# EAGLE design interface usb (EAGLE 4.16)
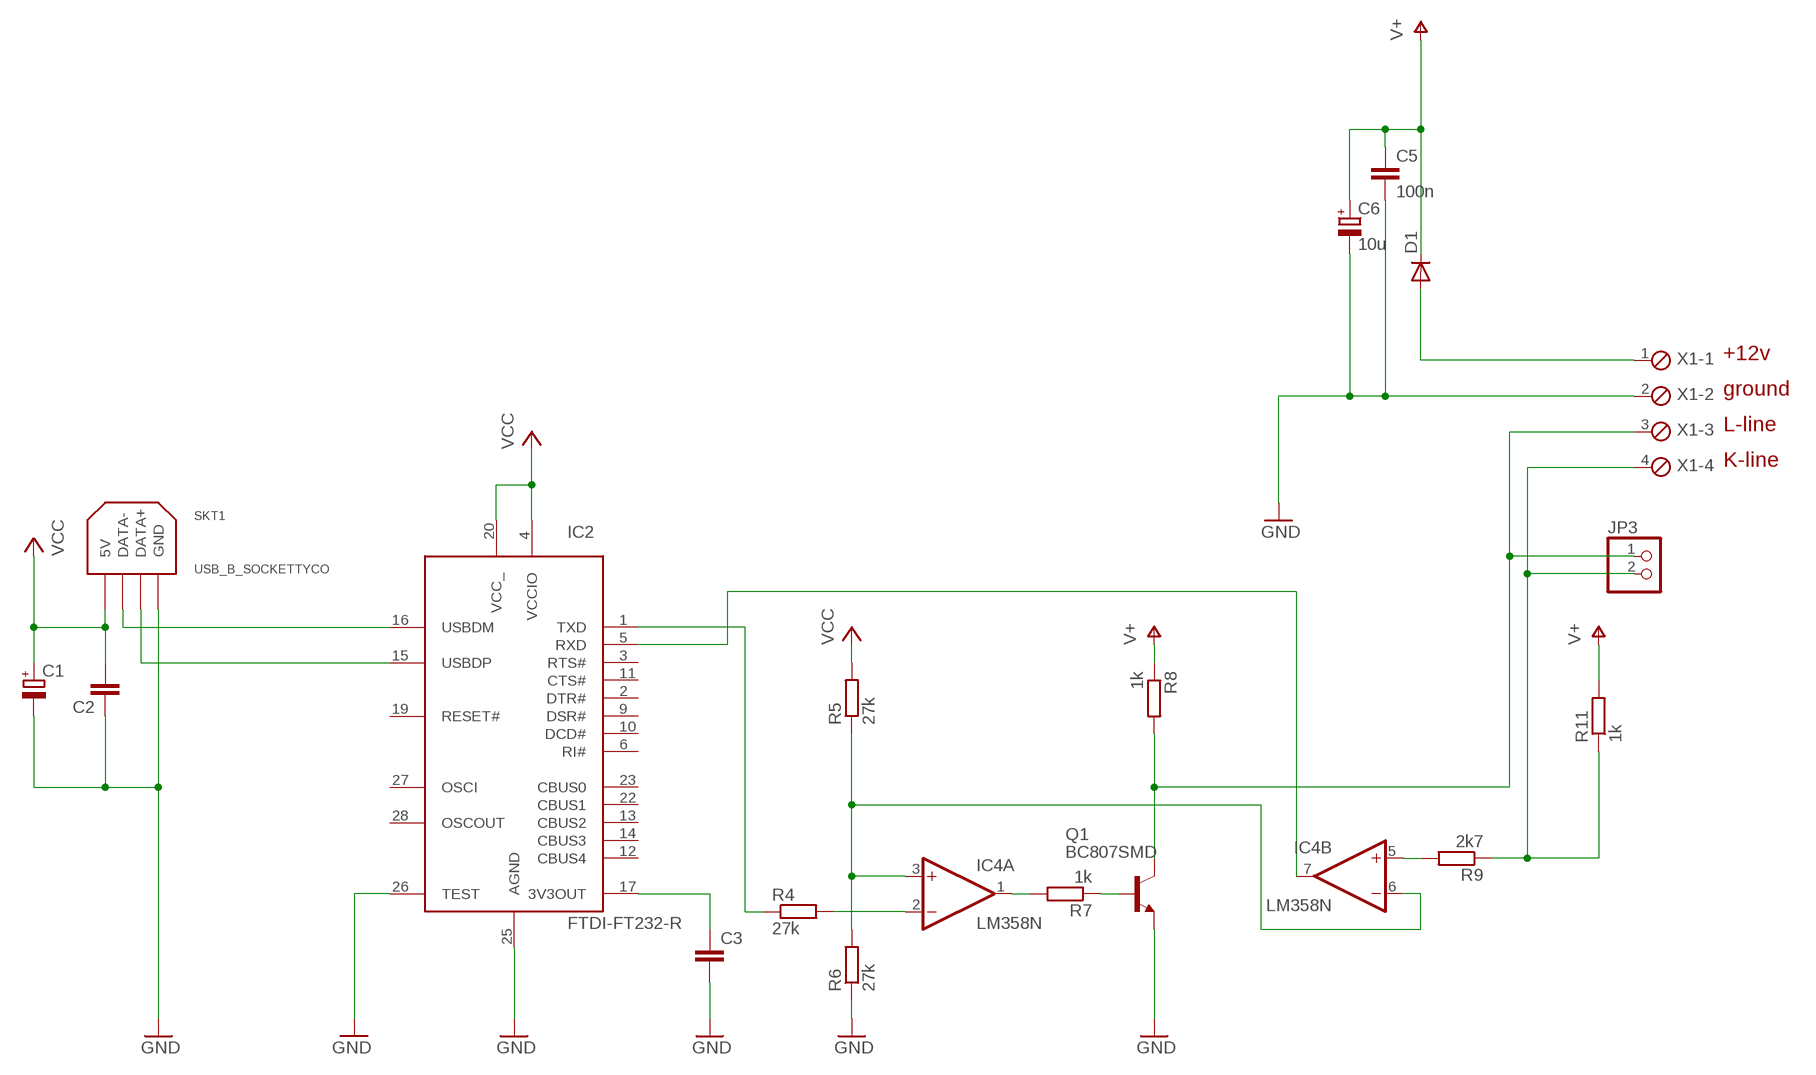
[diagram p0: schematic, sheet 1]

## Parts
C1  CPOL-EUC  [PANASONIC_C]
C2  C-EUC0805  [C0805]
C3  C-EUC0805  [C0805]
C5  100n  C-EUC0805  [C0805]
C6  10u  CPOL-EUC  [PANASONIC_C]
D1  DIODE-SOD80C  [SOD80C]
IC2  FTDI-FT232-R  [SSOP-28]
IC4  LM358N  LF353D  [SO08]
JP3  PINHD-1X2  [1X02]
Q1  BC807SMD  [SOT23-BEC]
R4  27k  R-EU_M0805  [M0805]
R5  27k  R-EU_M0805  [M0805]
R6  27k  R-EU_M0805  [M0805]
R7  1k  R-EU_M0805  [M0805]
R8  1k  R-EU_M0805  [M0805]
R9  2k7  R-EU_M0805  [M0805]
R11  1k  R-EU_M0805  [M0805]
SKT1  USB_B_SOCKETTYCO  [TYCO-USB-B]
X1  MPT4  [4POL254]

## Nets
GND: C1.- C2.1 C3.2 C5.2 C6.- IC2.25(AGND) IC2.26(TEST) Q1.E R6.1 SKT1.P$1(GND) X1.2
N$1: IC2.1(TXD) R4.1
N$2: C3.1 IC2.17(3V3OUT)
N$6: IC2.16(USBDM) SKT1.2(DATA-)
N$7: IC2.15(USBDP) SKT1.3(DATA+)
N$14: D1.A X1.1
N$15: JP3.2 R9.1 R11.1 X1.4
N$27: IC4.3(A:+IN) IC4.6(B:-IN) R5.1 R6.2
N$29: IC4.2(A:-IN) R4.2
N$30: IC4.1(A:OUT) R7.2
N$31: Q1.B R7.1
N$32: IC2.5(RXD) IC4.7(B:OUT)
N$33: JP3.1 Q1.C R8.2 X1.3
N$35: IC4.5(B:+IN) R9.2
V+: C5.1 C6.+ D1.C R8.1 R11.2
VCC: C1.+ C2.2 IC2.4(VCCIO) IC2.20(VCC_) R5.2 SKT1.1(5V)
Unconnected: IC2.2(DTR#) IC2.3(RTS#) IC2.6(RI#) IC2.9(DSR#) IC2.10(DCD#) IC2.11(CTS#) IC2.12(CBUS4) IC2.13(CBUS2) IC2.14(CBUS3) IC2.19(RESET#) IC2.22(CBUS1) IC2.23(CBUS0) IC2.27(OSCI) IC2.28(OSCOUT)

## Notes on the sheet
- +12v
- ground
- L-line
- K-line

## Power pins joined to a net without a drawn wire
GND: IC2.7(GND) IC2.18(GND) IC2.21(GND) IC4.4(GND) SKT1.4(GND) SKT1.P$2(GND)
VCC: IC4.8(VCC)

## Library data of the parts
C1 C6 = rcl:CPOL-EU: POLARIZED CAPACITOR, European symbol
C2 C3 C5 = rcl:C-EU: CAPACITOR, European symbol
D1 = diode:DIODE-: DIODE
IC2 = usb:FTDI-FT232-R
IC4 = linear:LF353: OP AMP
JP3 = pinhead:PINHD-1X2: PIN HEADER
Q1 = transistor-npn:BC807*: NPN Transistor
R4-R9 R11 = rcl:R-EU_: RESISTOR, European symbol
SKT1 = usb:USB_B_SOCKET
X1 = con-phoenix-254:MPT4: PHOENIX CONNECTOR

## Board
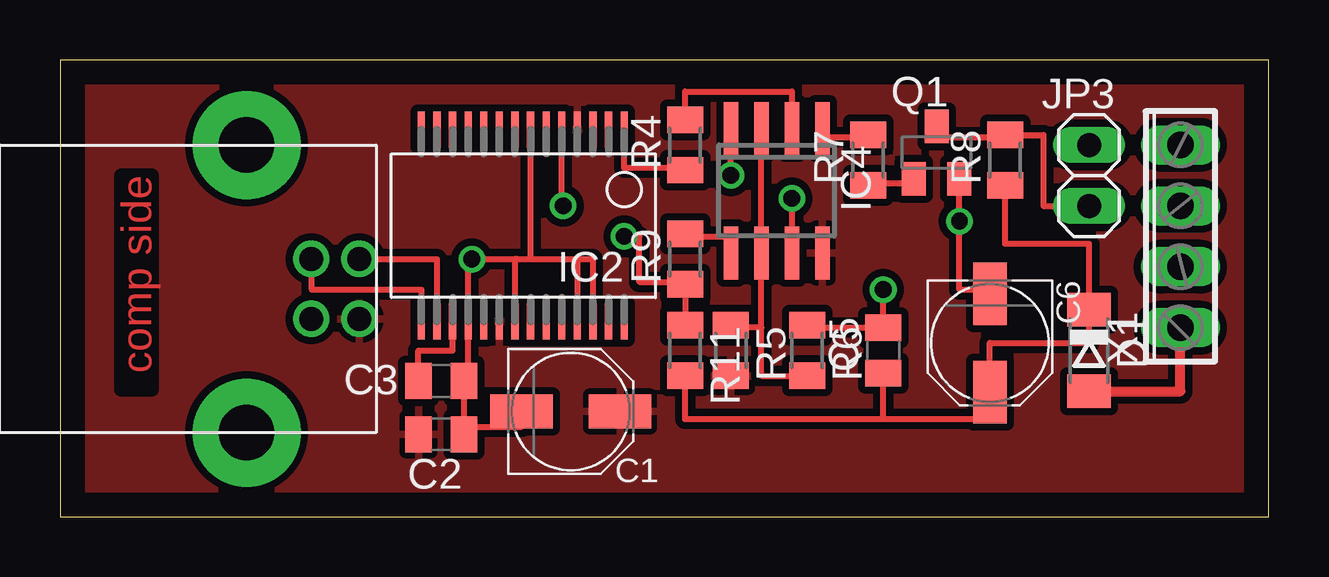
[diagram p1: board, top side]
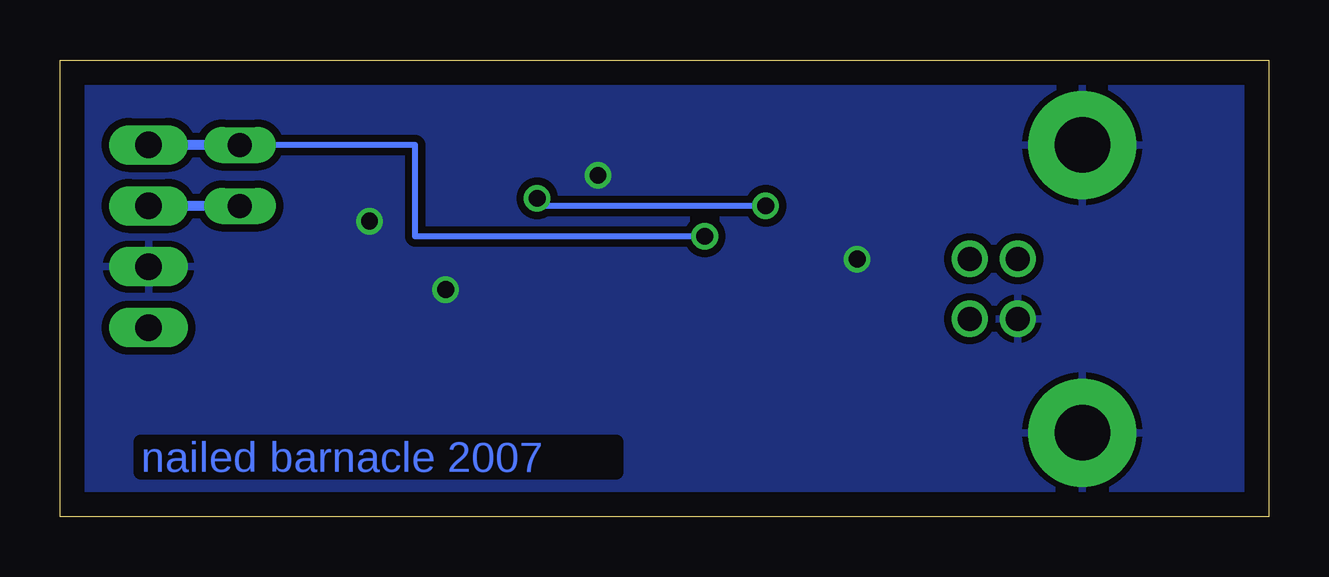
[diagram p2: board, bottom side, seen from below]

Size 50.37 x 19.05 mm. Coordinates in mm from the lower left corner, seen from the top.
Outline: 0,19.05 0,0 50.37,0 50.37,19.05 0,19.05
Copper layers (1*16): Top 0.035mm / dielectric 1.5mm / Bottom 0.035mm
Design rules "10mils": minimum track width 10mil, minimum drill 24mil, track to track 10mil, track to pad 10mil, pad to pad 10mil, via to via 10mil, smd to smd 10mil, copper to edge 40mil, drill to drill 10mil, minimum pad ring 10mil, minimum via ring 8mil, stop-mask expansion 0mil, vias tented up to drill 0mil, thermal gap 10mil

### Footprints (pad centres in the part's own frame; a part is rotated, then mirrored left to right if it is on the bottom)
PANASONIC_C = smd 2.6 x 1.4: + 2.05,0; - -2.05,0
C0805 = smd 1.1 x 1.5: 1 -0.95,0; 2 0.95,0
SOD80C = smd 1.4 x 1.8: A 1.7,0; C -1.7,0
SSOP-28 = smd 0.3 x 1.5: 1 0,0; 2 0.65,0; 3 1.3,0; 4 1.95,0; 5 2.6,0; 6 3.25,0; 7 3.9,0; 8 4.55,0; 9 5.2,0; 10 5.85,0; 11 6.5,0; 12 7.15,0; 13 7.8,0; 14 8.45,0; 15 8.45,8; 16 7.8,8; 17 7.15,8; 18 6.5,8; 19 5.85,8; 20 5.2,8; 21 4.55,8; 22 3.9,8; 23 3.25,8; 24 2.6,8; 25 1.95,8; 26 1.3,8; 27 0.65,8; 28 0,8
SO08 = smd 0.6 x 2.2: 1 -1.905,-2.6; 2 -0.635,-2.6; 3 0.635,-2.6; 4 1.905,-2.6; 5 1.905,2.6; 6 0.635,2.6; 7 -0.635,2.6; 8 -1.905,2.6
1X02 = drill 1 long: 1 -1.27,0; 2 1.27,0
SOT23-BEC = smd 1 x 1.4: B -0.95,-1.1; C 0,1.1; E 0.95,-1.1
M0805 = smd 1.1 x 1.5: 1 -1.05,0; 2 1.05,0
TYCO-USB-B = drill 1 round: 1 7.25,15; 2 4.75,15; 3 4.75,13; 4 7.25,13 | drill 2.3 pad 4.5 round: P$1 0,10.3; P$2 12,10.3
4POL254 = drill 1.1 long: 1 -3.81,0; 2 -1.27,0; 3 1.27,0; 4 3.81,0

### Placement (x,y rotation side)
C1  21.29,4.4 0 top
C2  15.89,3.44 180 top
C3  15.89,5.67 0 top
C5  34.3,6.94 90 top
C6  38.75,7.26 270 top
D1  42.88,6.94 270 top
IC2  23.51,16.14 180 top
IC4  29.86,13.6 180 top
JP3  42.88,14.24 90 top
Q1  36.53,15.19 0 top
R4  26.05,15.51 90 top
R5  27.95,6.94 270 top
R6  31.13,6.94 270 top
R7  33.67,14.88 90 top
R8  39.38,14.88 90 top
R9  26.05,10.75 90 top
R11  26.05,6.94 270 top
SKT1  -2.53,15.51 270 top
X1  46.69,11.7 90 top

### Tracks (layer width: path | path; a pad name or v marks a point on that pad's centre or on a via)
GND  (via drill 0.7)
  Top 0.254: C2.1 C3.2 17.01,5.67 IC2.18 17.01,10.75 v17.16,10.75 19.06,10.75 | C2.1 | C2.1 16.84,3.76 19.24,3.76 C1.- | 19.61,10.75 IC2.7 | 19.06,10.75 19.61,10.75 | IC2.26 22.21,10.75 21.6,10.75 | 19.61,10.75 21.6,10.75 | IC2.25 21.56,10.75 21.6,10.75 | IC2.21 18.96,10.75 19.06,10.75 | v27.95,14.24 IC4.4 | C5.2 v34.3,9.48 | Q1.E v37.48,12.33 37.48,9.48 38.75,9.48 C6.- | C5.2 | C5.2 34.3,7.99 | R6.1 31.13,7.89 C5.2
  pour Bottom (isolate 0.305): 0.33,18.69 0.33,0.27 49.54,0.27 49.54,18.69
N$1
  Top 0.254: R4.1 26.05,14.56 23.51,14.56 IC2.1
N$2
  Top 0.254: IC2.17 16.36,6.94 14.93,6.94 C3.1
N$6
  Top 0.254: 12.47,10.75 12.4,10.75 | SKT1.2 12.47,10.75 | IC2.16 15.71,10.75 12.47,10.75
N$7
  Top 0.254: IC2.15 15.06,9.48 10.49,9.48 10.49,10.75 10.47,10.75 SKT1.3
N$14
  Top 0.254: D1.A 42.87,5.35
  Top 0.406: D1.A 46.68,5.24 X1.1
N$15  (via drill 0.7)
  Top 0.254: R11.1 R9.1 26.05,9.8 24.14,9.8 24.14,11.7 v23.51,11.7
  Bottom 0.254: v23.51,11.7 35.57,11.7 35.57,15.51 JP3.2
  Bottom 0.406: JP3.2 X1.4
N$27
  Top 0.254: IC4.3 IC4.6 29.22,7.89 | R5.1 27.95,7.89 29.22,7.89 | R6.2 29.22,5.89 29.22,7.89
N$29
  Top 0.254: IC4.2 30.49,17.73 26.05,17.73 R4.2 26.05,16.46
N$30
  Top 0.254: R7.2 33.35,15.83 31.76,15.83 IC4.1
N$31
  Top 0.254: Q1.B 35.26,13.92 33.35,13.92 R7.1
N$32  (via drill 0.7)
  Top 0.254: v30.49,13.29 IC4.7 | IC2.5 20.91,12.97 v20.97,12.97
  Bottom 0.254: v30.49,13.29 30.49,12.97 v20.97,12.97
N$33
  Top 0.254: Q1.C 36.21,15.83 39.38,15.83 R8.2 40.97,15.92 40.97,12.97 JP3.1
  Bottom 0.406: JP3.1 X1.3
N$35
  Top 0.254: R9.2 26.05,11.7 27.95,11.7 IC4.5
V+
  Top 0.254: R8.1 39.38,11.38 42.87,11.38 D1.C 42.87,7.26 38.75,7.26 38.75,4.08 | 38.75,4.08 C6.+ | 34.3,4.08 C5.1 | 34.3,4.08 38.75,4.08 | R11.2 26.05,4.08 34.3,4.08
VCC
  pour Top (isolate 0.305): 0.33,18.69 0.33,0.27 49.54,0.27 49.54,18.69

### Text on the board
Top: comp side
Bottom: nailed barnacle 2007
